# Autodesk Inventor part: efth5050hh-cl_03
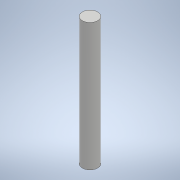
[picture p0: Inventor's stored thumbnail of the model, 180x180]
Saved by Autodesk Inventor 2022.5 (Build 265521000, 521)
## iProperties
Part Number: efth5050hh-cl_03
Material: 一般
Document SubType Name: Modeling
Designer: ImaoCorp
Density: 1 g/cm^3
Appearance: 既定
Author: ImaoCorp
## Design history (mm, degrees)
feature "efth5050hh-cl_03"
node "ソリッド1"
